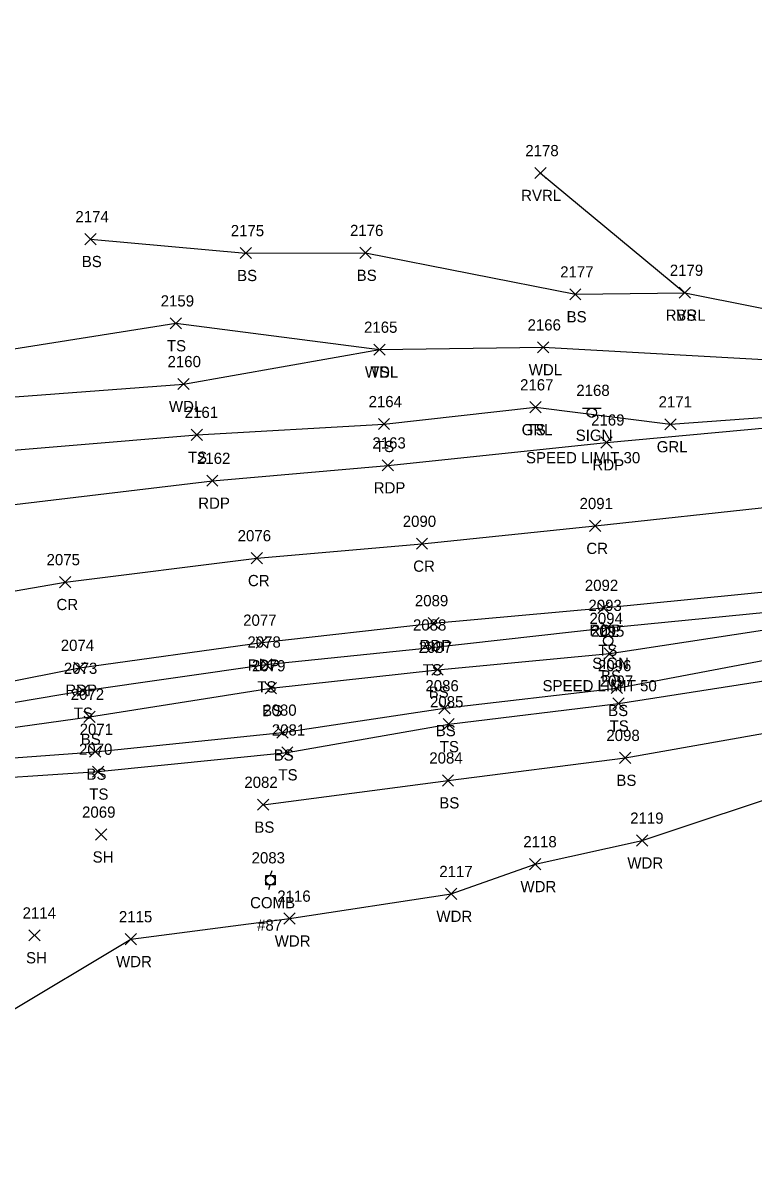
# Model space of a CAD drawing. Extents: x 1699408 to 1700423, y 840176 to 841410.
# Drawn here: x 1699637.2 to 1699767.4, y 840198.9 to 840403.9 of the extents above; entities that cross this region are included whole.
import ezdxf

# ---------------------------------------------------------------- set-up
doc = ezdxf.new("R2010")
doc.units = 0
for name, color, linetype in [('L_A', 7, 'Continuous'), ('L_I', 7, 'Continuous'), ('L_TIC', 7, 'Continuous'), ('LAWA', 7, 'Continuous'), ('LAWE', 7, 'Continuous'), ('LELB', 7, 'Continuous'), ('P_A', 7, 'Continuous'), ('P_I', 7, 'Continuous'), ('P_TIC', 7, 'Continuous'), ('PET', 7, 'Continuous'), ('PRC', 7, 'Continuous'), ('R_A', 7, 'Continuous'), ('R_I', 7, 'Continuous'), ('R_TIC', 7, 'Continuous'), ('RGR', 7, 'Continuous'), ('S_A', 7, 'Continuous'), ('S_C', 7, 'Continuous'), ('S_I', 7, 'Continuous'), ('SSGN', 7, 'Continuous'), ('U_A', 7, 'Continuous'), ('U_C', 7, 'Continuous'), ('U_I', 7, 'Continuous'), ('UP', 7, 'Continuous')]:
    doc.layers.add(name, color=color, linetype=linetype)

msp = doc.modelspace()

# ---------------------------------------------------------------- linework, layer by layer
at = {"layer": 'L_TIC'}
for points in [[(1699728.36, 840376.19), (1699730.36, 840378.19)], [(1699730.36, 840376.19), (1699728.36, 840378.19)], [(1699648.19, 840364.41), (1699650.19, 840366.41)], [(1699650.19, 840364.41), (1699648.19, 840366.41)], [(1699675.87, 840361.92), (1699677.87, 840363.92)], [(1699677.87, 840361.92), (1699675.87, 840363.92)], [(1699697.18, 840361.95), (1699699.18, 840363.95)], [(1699699.18, 840361.95), (1699697.18, 840363.95)], [(1699734.59, 840354.56), (1699736.59, 840356.56)], [(1699736.59, 840354.56), (1699734.59, 840356.56)], [(1699754.12, 840354.85), (1699756.12, 840356.85)], [(1699756.12, 840354.85), (1699754.12, 840356.85)], [(1699754.12, 840354.85), (1699756.12, 840356.85)], [(1699756.12, 840354.85), (1699754.12, 840356.85)], [(1699663.39, 840349.39), (1699665.39, 840351.39)], [(1699665.39, 840349.39), (1699663.39, 840351.39)], [(1699728.87, 840345.11), (1699730.87, 840347.11)], [(1699730.87, 840345.11), (1699728.87, 840347.11)], [(1699699.67, 840344.7), (1699701.67, 840346.7)], [(1699701.67, 840344.7), (1699699.67, 840346.7)], [(1699699.67, 840344.7), (1699701.67, 840346.7)], [(1699701.67, 840344.7), (1699699.67, 840346.7)], [(1699664.74, 840338.57), (1699666.74, 840340.57)], [(1699666.74, 840338.57), (1699664.74, 840340.57)], [(1699727.48, 840334.43), (1699729.48, 840336.43)], [(1699729.48, 840334.43), (1699727.48, 840336.43)], [(1699700.48, 840331.44), (1699702.48, 840333.44)], [(1699702.48, 840331.44), (1699700.48, 840333.44)], [(1699667.14, 840329.52), (1699669.14, 840331.52)], [(1699669.14, 840329.52), (1699667.14, 840331.52)], [(1699740.26, 840295.11), (1699742.26, 840297.11)], [(1699742.26, 840295.11), (1699740.26, 840297.11)], [(1699708.99, 840291.62), (1699710.99, 840293.62)], [(1699710.99, 840291.62), (1699708.99, 840293.62)], [(1699740.71, 840290.52), (1699742.71, 840292.52)], [(1699742.71, 840290.52), (1699740.71, 840292.52)], [(1699679.49, 840288.58), (1699681.49, 840290.58)], [(1699681.49, 840288.58), (1699679.49, 840290.58)], [(1699710.01, 840287.64), (1699712.01, 840289.64)], [(1699712.01, 840287.64), (1699710.01, 840289.64)], [(1699646.78, 840283.89), (1699648.78, 840285.89)], [(1699648.78, 840283.89), (1699646.78, 840285.89)], [(1699680.32, 840284.34), (1699682.32, 840286.34)], [(1699682.32, 840284.34), (1699680.32, 840286.34)], [(1699742, 840284.37), (1699744, 840286.37)], [(1699744, 840284.37), (1699742, 840286.37)], [(1699742.28, 840281.61), (1699744.28, 840283.61)], [(1699744.28, 840281.61), (1699742.28, 840283.61)], [(1699711.27, 840280.78), (1699713.27, 840282.78)], [(1699713.27, 840280.78), (1699711.27, 840282.78)], [(1699648, 840279.25), (1699650, 840281.25)], [(1699650, 840279.25), (1699648, 840281.25)], [(1699712.02, 840277.92), (1699714.02, 840279.92)], [(1699714.02, 840277.92), (1699712.02, 840279.92)], [(1699682.39, 840276.43), (1699684.39, 840278.43)], [(1699684.39, 840276.43), (1699682.39, 840278.43)], [(1699649.02, 840273.02), (1699651.02, 840275.02)], [(1699651.02, 840273.02), (1699649.02, 840275.02)], [(1699683.26, 840272.9), (1699685.26, 840274.9)], [(1699685.26, 840272.9), (1699683.26, 840274.9)], [(1699743.46, 840271.92), (1699745.46, 840273.92)], [(1699745.46, 840271.92), (1699743.46, 840273.92)], [(1699649.55, 840269.46), (1699651.55, 840271.46)], [(1699651.55, 840269.46), (1699649.55, 840271.46)], [(1699711.9, 840267.9), (1699713.9, 840269.9)], [(1699713.9, 840267.9), (1699711.9, 840269.9)], [(1699678.94, 840263.57), (1699680.94, 840265.57)], [(1699680.94, 840263.57), (1699678.94, 840265.57)], [(1699650.07, 840258.25), (1699652.07, 840260.25)], [(1699652.07, 840258.25), (1699650.07, 840260.25)], [(1699746.5, 840257.18), (1699748.5, 840259.18)], [(1699748.5, 840257.18), (1699746.5, 840259.18)], [(1699727.44, 840252.97), (1699729.44, 840254.97)], [(1699729.44, 840252.97), (1699727.44, 840254.97)], [(1699712.47, 840247.67), (1699714.47, 840249.67)], [(1699714.47, 840247.67), (1699712.47, 840249.67)], [(1699683.65, 840243.27), (1699685.65, 840245.27)], [(1699685.65, 840243.27), (1699683.65, 840245.27)], [(1699638.21, 840240.28), (1699640.21, 840242.28)], [(1699640.21, 840240.28), (1699638.21, 840242.28)], [(1699655.37, 840239.6), (1699657.37, 840241.6)], [(1699657.37, 840239.6), (1699655.37, 840241.6)]]:
    msp.add_lwpolyline(points, dxfattribs=at)
at = {"layer": 'LAWA'}
for points in [[(1699556.13, 840340.53), (1699588.5, 840337.27), (1699620.6, 840336.18), (1699665.74, 840339.57), (1699700.67, 840345.7), (1699729.87, 840346.11), (1699784.06, 840343.1)], [(1699633.39, 840226.83), (1699656.37, 840240.6), (1699684.65, 840244.27), (1699713.47, 840248.67), (1699728.44, 840253.97), (1699747.5, 840258.18), (1699776.61, 840267.9), (1699816.97, 840275.18), (1699846.39, 840276.57)]]:
    msp.add_lwpolyline(points, dxfattribs=at)
at = {"layer": 'LAWE'}
msp.add_lwpolyline([(1699729.36, 840377.19), (1699755.12, 840355.85), (1699780.74, 840350.74), (1699821.29, 840354.82), (1699849, 840359.49), (1699872.08, 840366.87), (1699889.41, 840374.37), (1699901.94, 840377.56)], dxfattribs=at)
at = {"layer": 'LELB'}
for points in [[(1699649.19, 840365.41), (1699676.87, 840362.92), (1699698.18, 840362.95), (1699735.59, 840355.56), (1699755.12, 840355.85)], [(1699554.51, 840347.54), (1699585.63, 840351.68), (1699620.87, 840343.53), (1699664.39, 840350.39), (1699700.67, 840345.7)], [(1699479.81, 840326.06), (1699519.34, 840326.61), (1699568.26, 840329.58), (1699587.28, 840330.32), (1699620.45, 840326.5), (1699668.14, 840330.52), (1699701.48, 840332.44), (1699728.48, 840335.43)], [(1699449.32, 840203.24), (1699477.66, 840221.47), (1699508.6, 840240.03), (1699538.28, 840254.01), (1699565.8, 840264.7), (1699593.44, 840273.59), (1699619.93, 840280.17), (1699647.78, 840284.89), (1699680.49, 840289.58), (1699709.99, 840292.62), (1699741.26, 840296.11), (1699773.28, 840299.24), (1699807.33, 840304.54), (1699837.32, 840309.49), (1699840.77, 840304.78), (1699846.98, 840289.91), (1699852.46, 840279.79)], [(1699450.68, 840200.86), (1699478.43, 840220.04), (1699510.71, 840237.45), (1699539.18, 840250.98), (1699567.45, 840262.15), (1699594.13, 840270.62), (1699621.67, 840276.44), (1699649, 840280.25), (1699681.32, 840285.34), (1699711.01, 840288.64), (1699741.71, 840291.52), (1699773.21, 840296.35), (1699808.7, 840300.3), (1699836.43, 840305.42), (1699838.09, 840303.05), (1699840.88, 840298.91), (1699844.69, 840290.05), (1699850.95, 840279.03)], [(1699452.04, 840198.91), (1699479.59, 840217.72), (1699512.19, 840235.39), (1699539.84, 840249.47), (1699568.3, 840260.42), (1699595.02, 840268.85), (1699623.34, 840272.03), (1699650.02, 840274.02), (1699683.39, 840277.43), (1699712.27, 840281.78), (1699743, 840285.37), (1699773.99, 840291.21), (1699809.19, 840296.39), (1699836.05, 840299.39), (1699842.76, 840289.31), (1699848.51, 840278.09)], [(1699623.59, 840268.72), (1699650.55, 840270.46), (1699684.26, 840273.9), (1699713.02, 840278.92), (1699743.28, 840282.61), (1699774.87, 840287.54), (1699810.2, 840292.51), (1699837.06, 840294.28), (1699841.18, 840284.12), (1699846.39, 840276.57)], [(1699679.94, 840264.57), (1699712.9, 840268.9), (1699744.46, 840272.92), (1699774.99, 840278.35), (1699812.08, 840284.69), (1699841.18, 840284.12)]]:
    msp.add_lwpolyline(points, dxfattribs=at)
at = {"layer": 'P_TIC'}
for points in [[(1699740.15, 840328.16), (1699742.15, 840330.16)], [(1699742.15, 840328.16), (1699740.15, 840330.16)], [(1699701.16, 840324.07), (1699703.16, 840326.07)], [(1699703.16, 840324.07), (1699701.16, 840326.07)], [(1699669.9, 840321.33), (1699671.9, 840323.33)], [(1699671.9, 840321.33), (1699669.9, 840323.33)], [(1699738.11, 840313.27), (1699740.11, 840315.27)], [(1699740.11, 840313.27), (1699738.11, 840315.27)], [(1699707.26, 840310.1), (1699709.26, 840312.1)], [(1699709.26, 840310.1), (1699707.26, 840312.1)], [(1699677.81, 840307.53), (1699679.81, 840309.53)], [(1699679.81, 840307.53), (1699677.81, 840309.53)], [(1699643.68, 840303.26), (1699645.68, 840305.26)], [(1699645.68, 840303.26), (1699643.68, 840305.26)], [(1699739.62, 840298.68), (1699741.62, 840300.68)], [(1699741.62, 840298.68), (1699739.62, 840300.68)], [(1699709.33, 840295.95), (1699711.33, 840297.95)], [(1699711.33, 840295.95), (1699709.33, 840297.95)], [(1699678.73, 840292.47), (1699680.73, 840294.47)], [(1699680.73, 840292.47), (1699678.73, 840294.47)], [(1699646.22, 840287.99), (1699648.22, 840289.99)], [(1699648.22, 840287.99), (1699646.22, 840289.99)]]:
    msp.add_lwpolyline(points, dxfattribs=at)
at = {"layer": 'PET'}
for points in [[(1699430.72, 840228.22), (1699466.92, 840252.65), (1699493.58, 840268.87), (1699501.63, 840273.58), (1699505.33, 840277.49), (1699516.37, 840283.58), (1699542.26, 840294.23), (1699569.87, 840304.55), (1699598.29, 840312.45), (1699620.64, 840316.32), (1699670.9, 840322.33), (1699702.16, 840325.07), (1699741.15, 840329.16), (1699780.55, 840332.75), (1699814.05, 840338.23), (1699848.8, 840345.35), (1699873.3, 840351.35), (1699914.22, 840362.32), (1699930.57, 840367.02), (1699959.45, 840375.82), (1699990.91, 840385.72), (1700021.62, 840396.71), (1700043.81, 840403.93)], [(1699447.11, 840206.16), (1699475.63, 840224.65), (1699506.94, 840242.78), (1699536.09, 840256.08), (1699564.51, 840267.73), (1699591.88, 840277.12), (1699619.21, 840283.47), (1699647.22, 840288.99), (1699679.73, 840293.47), (1699710.33, 840296.95), (1699740.62, 840299.68), (1699772.35, 840302.79), (1699806.37, 840308.43), (1699836.08, 840313.39), (1699858.12, 840318.39), (1699877.08, 840323.18), (1699900.35, 840329.36), (1699935.97, 840340.61), (1699968.58, 840349.28), (1700000.7, 840359.42), (1700031.35, 840369.03)]]:
    msp.add_lwpolyline(points, dxfattribs=at)
at = {"layer": 'PRC'}
msp.add_lwpolyline([(1699438.11, 840217.33), (1699474.74, 840241.27), (1699500.34, 840255.97), (1699530.26, 840270.89), (1699558.33, 840282.59), (1699589.24, 840292.75), (1699616.86, 840299.45), (1699644.68, 840304.26), (1699678.81, 840308.53), (1699708.26, 840311.1), (1699739.11, 840314.27), (1699770.93, 840317.73), (1699804.23, 840322.43), (1699833.64, 840328), (1699873.5, 840337.02), (1699896.6, 840342.97), (1699933.32, 840353.07), (1699963.1, 840362.17), (1699996.81, 840372.51), (1700026.94, 840382.38)], dxfattribs=at)
at = {"layer": 'R_TIC'}
for points in [[(1699727.48, 840334.43), (1699729.48, 840336.43)], [(1699729.48, 840334.43), (1699727.48, 840336.43)], [(1699751.54, 840331.39), (1699753.54, 840333.39)], [(1699753.54, 840331.39), (1699751.54, 840333.39)]]:
    msp.add_lwpolyline(points, dxfattribs=at)
at = {"layer": 'RGR'}
msp.add_lwpolyline([(1699728.48, 840335.43), (1699752.54, 840332.39), (1699780.34, 840334.41), (1699813.44, 840339.9), (1699849.41, 840347.4), (1699873.97, 840353.47), (1699916.95, 840364.91), (1699929.95, 840368.59), (1699959.73, 840377.35), (1699990.11, 840387.92), (1700008.42, 840397.8)], dxfattribs=at)
at = {"layer": 'SSGN'}
for p, q in [((1699736.87, 840335.29), (1699740.21, 840335.29)), ((1699738.52, 840334.46), (1699738.52, 840334.46)), ((1699739.82, 840294.64), (1699743.15, 840294.64)), ((1699741.46, 840293.8), (1699741.46, 840293.8))]:
    msp.add_line(p, q, dxfattribs=at)
for centre in [(1699738.52, 840334.46), (1699741.46, 840293.8)]:
    msp.add_circle(centre, 0.833, dxfattribs=at)
at = {"layer": 'UP'}
for p, q in [((1699681.48, 840252.77), (1699681.23, 840251.94)), ((1699680.4, 840250.27), (1699680.4, 840251.94)), ((1699680.4, 840251.94), (1699682.07, 840251.94)), ((1699681.23, 840251.1), (1699681.23, 840251.1)), ((1699682.07, 840251.94), (1699682.07, 840250.27)), ((1699682.07, 840250.27), (1699680.4, 840250.27)), ((1699680.98, 840249.44), (1699681.23, 840250.27))]:
    msp.add_line(p, q, dxfattribs=at)
msp.add_circle((1699681.23, 840251.1), 0.833, dxfattribs=at)

# ---------------------------------------------------------------- texts
at = {"layer": 'L_A'}
for s, p in [('RVRL', (1699725.93, 840372.19)), ('BS', (1699647.63, 840360.41)), ('BS', (1699675.31, 840357.92)), ('BS', (1699696.62, 840357.95)), ('BS', (1699734.03, 840350.56)), ('RVRL', (1699751.68, 840350.85)), ('BS', (1699753.56, 840350.85)), ('TS', (1699662.8, 840345.39)), ('WDL', (1699727.28, 840341.11)), ('WDL', (1699698.09, 840340.7)), ('TS', (1699699.08, 840340.7)), ('WDL', (1699663.16, 840334.57)), ('TS', (1699726.89, 840330.43)), ('TS', (1699699.89, 840327.44)), ('TS', (1699666.55, 840325.52)), ('TS', (1699739.66, 840291.11)), ('TS', (1699708.4, 840287.62)), ('BS', (1699740.15, 840286.52)), ('TS', (1699678.9, 840284.58)), ('BS', (1699709.45, 840283.64)), ('TS', (1699646.19, 840279.89)), ('BS', (1699679.76, 840280.34)), ('BS', (1699741.44, 840280.37)), ('TS', (1699741.69, 840277.61)), ('BS', (1699647.44, 840275.25)), ('BS', (1699710.71, 840276.78)), ('TS', (1699711.43, 840273.92)), ('BS', (1699681.83, 840272.43)), ('BS', (1699648.46, 840269.02)), ('TS', (1699682.67, 840268.9)), ('BS', (1699742.9, 840267.92)), ('TS', (1699648.96, 840265.46)), ('BS', (1699711.34, 840263.9)), ('BS', (1699678.38, 840259.57)), ('SH', (1699649.56, 840254.25)), ('WDR', (1699744.86, 840253.18)), ('WDR', (1699725.81, 840248.97)), ('WDR', (1699710.83, 840243.67)), ('WDR', (1699682.01, 840239.27)), ('SH', (1699637.69, 840236.28)), ('WDR', (1699653.73, 840235.6))]:
    msp.add_text(s, height=2, dxfattribs=at).set_placement(p)
at = {"layer": 'L_I'}
for s, p in [('2178', (1699726.67, 840380.19)), ('2174', (1699646.49, 840368.41)), ('2175', (1699674.18, 840365.92)), ('2176', (1699695.43, 840365.95)), ('2177', (1699732.89, 840358.56)), ('2179', (1699752.42, 840358.85)), ('2179', (1699752.42, 840358.85)), ('2159', (1699661.69, 840353.39)), ('2166', (1699727.07, 840349.11)), ('2165', (1699697.93, 840348.7)), ('2165', (1699697.93, 840348.7)), ('2160', (1699662.91, 840342.57)), ('2167', (1699725.74, 840338.43)), ('2164', (1699698.74, 840335.44)), ('2161', (1699665.97, 840333.52)), ('2093', (1699737.92, 840299.11)), ('2088', (1699706.65, 840295.62)), ('2095', (1699738.37, 840294.52)), ('2078', (1699677.15, 840292.58)), ('2087', (1699707.67, 840291.64)), ('2073', (1699644.44, 840287.89)), ('2079', (1699677.97, 840288.34)), ('2096', (1699739.61, 840288.37)), ('2097', (1699739.95, 840285.61)), ('2086', (1699708.87, 840284.78)), ('2072', (1699645.66, 840283.25)), ('2085', (1699709.69, 840281.92)), ('2080', (1699679.96, 840280.43)), ('2071', (1699647.25, 840277.02)), ('2081', (1699681.49, 840276.9)), ('2098', (1699741.12, 840275.92)), ('2070', (1699647.13, 840273.46)), ('2084', (1699709.56, 840271.9)), ('2082', (1699676.6, 840267.57)), ('2069', (1699647.68, 840262.25)), ('2119', (1699745.36, 840261.18)), ('2118', (1699726.32, 840256.97)), ('2117', (1699711.34, 840251.67)), ('2116', (1699682.47, 840247.27)), ('2114', (1699637.08, 840244.28)), ('2115', (1699654.24, 840243.6))]:
    msp.add_text(s, height=2, dxfattribs=at).set_placement(p)
at = {"layer": 'P_A'}
for s, p in [('RDP', (1699738.64, 840324.16)), ('RDP', (1699699.65, 840320.07)), ('RDP', (1699668.38, 840317.33)), ('CR', (1699737.55, 840309.27)), ('CR', (1699706.69, 840306.1)), ('CR', (1699677.24, 840303.53)), ('CR', (1699643.12, 840299.26)), ('RDP', (1699738.11, 840294.68)), ('RDP', (1699707.82, 840291.95)), ('RDP', (1699677.22, 840288.47)), ('RDP', (1699644.7, 840283.99))]:
    msp.add_text(s, height=2, dxfattribs=at).set_placement(p)
at = {"layer": 'P_I'}
for s, p in [('2169', (1699738.4, 840332.16)), ('2163', (1699699.42, 840328.07)), ('2162', (1699668.16, 840325.33)), ('2091', (1699736.34, 840317.27)), ('2090', (1699704.83, 840314.1)), ('2076', (1699675.41, 840311.53)), ('2075', (1699641.35, 840307.26)), ('2092', (1699737.28, 840302.68)), ('2089', (1699706.99, 840299.95)), ('2077', (1699676.39, 840296.47)), ('2074', (1699643.88, 840291.99))]:
    msp.add_text(s, height=2, dxfattribs=at).set_placement(p)
at = {"layer": 'R_A'}
for p in [(1699726.02, 840330.43), (1699750.09, 840327.39)]:
    msp.add_text('GRL', height=2, dxfattribs=at).set_placement(p)
at = {"layer": 'R_I'}
for s, p in [('2167', (1699725.74, 840338.43)), ('2171', (1699750.42, 840335.39))]:
    msp.add_text(s, height=2, dxfattribs=at).set_placement(p)
at = {"layer": 'S_A'}
for p in [(1699735.66, 840329.44), (1699738.6, 840288.78)]:
    msp.add_text('SIGN', height=2, dxfattribs=at).set_placement(p)
at = {"layer": 'S_C'}
for s, p in [('SPEED LIMIT 30', (1699726.79, 840325.44)), ('SPEED LIMIT 50', (1699729.74, 840284.78))]:
    msp.add_text(s, height=2, dxfattribs=at).set_placement(p)
at = {"layer": 'S_I'}
for s, p in [('2168', (1699735.76, 840337.44)), ('2094', (1699738.11, 840296.78))]:
    msp.add_text(s, height=2, dxfattribs=at).set_placement(p)
at = {"layer": 'U_A'}
msp.add_text('COMB', height=2, dxfattribs=at).set_placement((1699677.62, 840246.1))
at = {"layer": 'U_C'}
msp.add_text('#87', height=2, dxfattribs=at).set_placement((1699678.87, 840242.1))
at = {"layer": 'U_I'}
msp.add_text('2083', height=2, dxfattribs=at).set_placement((1699677.89, 840254.1))

doc.saveas('drawing.dxf')
